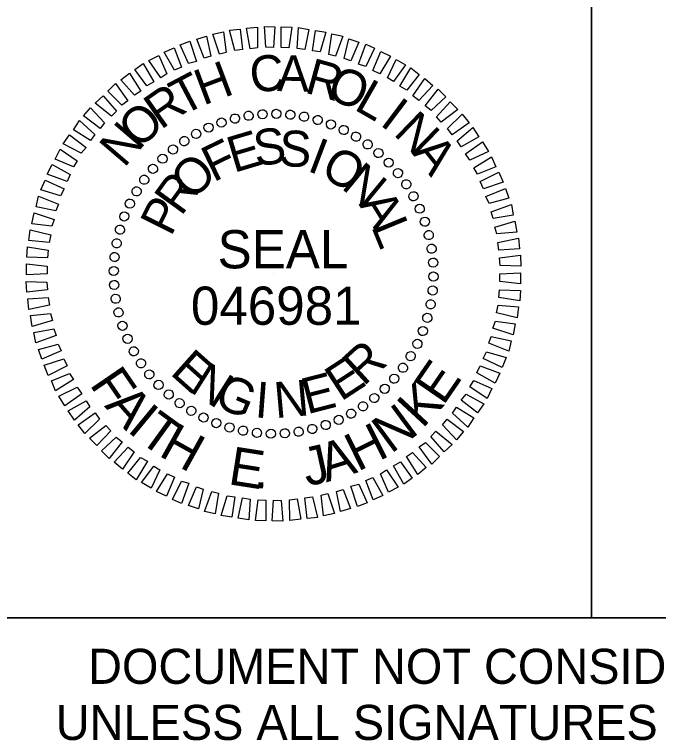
# Model space of a CAD drawing. Extents: x 1629787 to 1631995, y 1166253 to 1167353.
# Drawn here: x 1631263.8 to 1631364.8, y 1167171.6 to 1167285.5 of the extents above; entities that cross this region are included whole.
import ezdxf

# ---------------------------------------------------------------- set-up
doc = ezdxf.new("R2010")
doc.units = 0
for name, color, linetype in [('Sheet PE Seal Cell', 7, 'Continuous'), ('Sheet Profile CELL', 7, 'Continuous'), ('Sheet Sticker Exception Certification CELL', 7, 'Continuous')]:
    doc.layers.add(name, color=color, linetype=linetype)

msp = doc.modelspace()

# ---------------------------------------------------------------- linework, layer by layer
at = {"layer": 'Sheet PE Seal Cell'}
for p, q in [((1631300.53, 1167269.56), (1631300.53, 1167269.56)), ((1631302.68, 1167269.86), (1631302.68, 1167269.86)), ((1631304.88, 1167269.91), (1631304.88, 1167269.91)), ((1631307.08, 1167269.76), (1631307.08, 1167269.76)), ((1631309.23, 1167269.41), (1631309.23, 1167269.41)), ((1631296.23, 1167268.56), (1631296.23, 1167268.56)), ((1631298.33, 1167269.16), (1631298.33, 1167269.16)), ((1631311.33, 1167268.96), (1631311.33, 1167268.96)), ((1631313.43, 1167268.26), (1631313.43, 1167268.26)), ((1631294.23, 1167267.76), (1631294.23, 1167267.76)), ((1631315.43, 1167267.36), (1631315.43, 1167267.36)), ((1631292.28, 1167266.76), (1631292.28, 1167266.76)), ((1631317.38, 1167266.36), (1631317.38, 1167266.36)), ((1631290.38, 1167265.61), (1631290.38, 1167265.61)), ((1631319.18, 1167265.11), (1631319.18, 1167265.11)), ((1631288.63, 1167264.36), (1631288.63, 1167264.36)), ((1631320.93, 1167263.76), (1631320.93, 1167263.76)), ((1631286.98, 1167262.86), (1631286.98, 1167262.86)), ((1631285.48, 1167261.31), (1631285.48, 1167261.31)), ((1631322.48, 1167262.26), (1631322.48, 1167262.26)), ((1631323.98, 1167260.61), (1631323.98, 1167260.61)), ((1631284.13, 1167259.56), (1631284.13, 1167259.56)), ((1631325.23, 1167258.86), (1631325.23, 1167258.86)), ((1631282.88, 1167257.76), (1631282.88, 1167257.76)), ((1631326.38, 1167256.96), (1631326.38, 1167256.96)), ((1631281.88, 1167255.81), (1631281.88, 1167255.81)), ((1631327.38, 1167255.01), (1631327.38, 1167255.01)), ((1631280.98, 1167253.81), (1631280.98, 1167253.81)), ((1631328.18, 1167253.01), (1631328.18, 1167253.01)), ((1631280.28, 1167251.71), (1631280.28, 1167251.71)), ((1631328.78, 1167250.91), (1631328.78, 1167250.91)), ((1631279.83, 1167249.61), (1631279.83, 1167249.61)), ((1631329.18, 1167248.71), (1631329.18, 1167248.71)), ((1631279.48, 1167247.46), (1631279.48, 1167247.46)), ((1631329.48, 1167246.56), (1631329.48, 1167246.56)), ((1631279.33, 1167245.26), (1631279.33, 1167245.26)), ((1631304.43, 1167244.81), (1631304.43, 1167244.81)), ((1631329.53, 1167244.36), (1631329.53, 1167244.36)), ((1631279.38, 1167243.06), (1631279.38, 1167243.06)), ((1631329.38, 1167242.16), (1631329.38, 1167242.16)), ((1631279.68, 1167240.91), (1631279.68, 1167240.91)), ((1631329.03, 1167240.01), (1631329.03, 1167240.01)), ((1631280.08, 1167238.71), (1631280.08, 1167238.71)), ((1631328.58, 1167237.91), (1631328.58, 1167237.91)), ((1631280.68, 1167236.61), (1631280.68, 1167236.61)), ((1631327.88, 1167235.81), (1631327.88, 1167235.81)), ((1631281.48, 1167234.61), (1631281.48, 1167234.61)), ((1631326.98, 1167233.81), (1631326.98, 1167233.81)), ((1631282.48, 1167232.66), (1631282.48, 1167232.66)), ((1631325.98, 1167231.86), (1631325.98, 1167231.86)), ((1631283.63, 1167230.76), (1631283.63, 1167230.76)), ((1631324.73, 1167230.06), (1631324.73, 1167230.06)), ((1631284.88, 1167229.01), (1631284.88, 1167229.01)), ((1631323.38, 1167228.31), (1631323.38, 1167228.31)), ((1631286.38, 1167227.36), (1631286.38, 1167227.36)), ((1631321.88, 1167226.76), (1631321.88, 1167226.76)), ((1631287.93, 1167225.86), (1631287.93, 1167225.86)), ((1631320.23, 1167225.26), (1631320.23, 1167225.26)), ((1631289.68, 1167224.51), (1631289.68, 1167224.51)), ((1631318.48, 1167224.01), (1631318.48, 1167224.01)), ((1631291.48, 1167223.26), (1631291.48, 1167223.26)), ((1631316.58, 1167222.86), (1631316.58, 1167222.86)), ((1631293.43, 1167222.26), (1631293.43, 1167222.26)), ((1631314.63, 1167221.86), (1631314.63, 1167221.86)), ((1631295.43, 1167221.36), (1631295.43, 1167221.36)), ((1631297.53, 1167220.66), (1631297.53, 1167220.66)), ((1631310.53, 1167220.46), (1631310.53, 1167220.46)), ((1631312.63, 1167221.06), (1631312.63, 1167221.06)), ((1631299.63, 1167220.21), (1631299.63, 1167220.21)), ((1631301.78, 1167219.86), (1631301.78, 1167219.86)), ((1631303.98, 1167219.71), (1631303.98, 1167219.71)), ((1631306.18, 1167219.76), (1631306.18, 1167219.76)), ((1631308.33, 1167220.06), (1631308.33, 1167220.06))]:
    msp.add_line(p, q, dxfattribs=at)
for points in [[(1631298.33, 1167279.81), (1631297.53, 1167283.01), (1631299.18, 1167283.16), (1631299.53, 1167279.96)], [(1631300.73, 1167280.11), (1631300.18, 1167283.31), (1631301.88, 1167283.51), (1631301.93, 1167280.26)], [(1631303.23, 1167280.36), (1631302.98, 1167283.61), (1631304.63, 1167283.56), (1631304.43, 1167280.31)], [(1631305.63, 1167280.31), (1631305.63, 1167283.56), (1631307.28, 1167283.51), (1631306.83, 1167280.26)], [(1631308.13, 1167280.16), (1631308.33, 1167283.41), (1631309.98, 1167283.11), (1631309.33, 1167279.96)], [(1631310.53, 1167279.76), (1631310.98, 1167282.96), (1631312.63, 1167282.71), (1631311.73, 1167279.61)], [(1631293.53, 1167278.61), (1631292.38, 1167281.61), (1631293.93, 1167282.06), (1631294.58, 1167278.96)], [(1631295.93, 1167279.26), (1631294.88, 1167282.41), (1631296.58, 1167282.76), (1631296.98, 1167279.51)], [(1631313.08, 1167279.21), (1631313.58, 1167282.46), (1631315.28, 1167282.06), (1631314.13, 1167278.96)], [(1631291.08, 1167277.81), (1631289.78, 1167280.71), (1631291.28, 1167281.31), (1631292.33, 1167278.11)], [(1631315.48, 1167278.56), (1631316.23, 1167281.66), (1631317.78, 1167281.16), (1631316.53, 1167278.21)], [(1631317.73, 1167277.66), (1631318.88, 1167280.81), (1631320.28, 1167280.21), (1631318.88, 1167277.31)], [(1631288.88, 1167276.76), (1631287.28, 1167279.56), (1631288.83, 1167280.26), (1631289.98, 1167277.21)], [(1631319.98, 1167276.71), (1631321.23, 1167279.66), (1631322.78, 1167278.96), (1631321.08, 1167276.16)], [(1631286.73, 1167275.56), (1631284.88, 1167278.26), (1631286.43, 1167279.06), (1631287.68, 1167276.16)], [(1631322.28, 1167275.56), (1631323.63, 1167278.41), (1631325.13, 1167277.56), (1631323.23, 1167274.96)], [(1631284.53, 1167274.31), (1631282.68, 1167276.86), (1631283.98, 1167277.81), (1631285.63, 1167274.91)], [(1631282.63, 1167272.81), (1631280.48, 1167275.21), (1631281.83, 1167276.26), (1631283.58, 1167273.46)], [(1631324.23, 1167274.21), (1631325.98, 1167277.11), (1631327.28, 1167276.06), (1631325.33, 1167273.61)], [(1631326.28, 1167272.71), (1631328.13, 1167275.46), (1631329.43, 1167274.36), (1631327.23, 1167272.01)], [(1631280.63, 1167271.26), (1631278.43, 1167273.46), (1631279.63, 1167274.66), (1631281.58, 1167271.96)], [(1631328.18, 1167271.16), (1631330.23, 1167273.76), (1631331.43, 1167272.56), (1631329.13, 1167270.41)], [(1631278.98, 1167269.51), (1631276.43, 1167271.56), (1631277.68, 1167272.71), (1631279.78, 1167270.31)], [(1631329.98, 1167269.41), (1631332.13, 1167271.76), (1631333.33, 1167270.56), (1631330.73, 1167268.61)], [(1631277.23, 1167267.61), (1631274.63, 1167269.56), (1631275.73, 1167270.86), (1631277.93, 1167268.51)], [(1631331.73, 1167267.61), (1631334.03, 1167269.86), (1631335.08, 1167268.51), (1631332.43, 1167266.61)], [(1631275.73, 1167265.71), (1631273.03, 1167267.41), (1631273.98, 1167268.86), (1631276.38, 1167266.66)], [(1631333.23, 1167265.66), (1631335.68, 1167267.76), (1631336.63, 1167266.31), (1631333.83, 1167264.71)], [(1631274.23, 1167263.71), (1631271.43, 1167265.21), (1631272.43, 1167266.61), (1631275.03, 1167264.61)], [(1631334.53, 1167263.61), (1631337.18, 1167265.51), (1631338.13, 1167264.01), (1631335.23, 1167262.61)], [(1631273.03, 1167261.56), (1631270.18, 1167262.81), (1631270.93, 1167264.36), (1631273.63, 1167262.51)], [(1631335.83, 1167261.41), (1631338.63, 1167263.16), (1631339.28, 1167261.61), (1631336.43, 1167260.46)], [(1631272.03, 1167259.26), (1631268.93, 1167260.41), (1631269.68, 1167261.96), (1631272.53, 1167260.36)], [(1631336.83, 1167259.26), (1631339.78, 1167260.76), (1631340.43, 1167259.16), (1631337.33, 1167258.16)], [(1631271.03, 1167257.06), (1631267.93, 1167257.96), (1631268.58, 1167259.51), (1631271.58, 1167258.11)], [(1631337.73, 1167256.91), (1631340.78, 1167258.21), (1631341.33, 1167256.66), (1631338.23, 1167255.86)], [(1631270.28, 1167254.66), (1631267.18, 1167255.31), (1631267.53, 1167256.96), (1631270.68, 1167255.71)], [(1631338.53, 1167254.51), (1631341.73, 1167255.66), (1631342.03, 1167254.01), (1631338.88, 1167253.46)], [(1631269.63, 1167252.26), (1631266.53, 1167252.66), (1631266.88, 1167254.36), (1631270.03, 1167253.31)], [(1631339.13, 1167252.11), (1631342.28, 1167253.06), (1631342.58, 1167251.36), (1631339.43, 1167251.06)], [(1631269.23, 1167249.71), (1631266.03, 1167250.01), (1631266.23, 1167251.71), (1631269.48, 1167250.91)], [(1631339.58, 1167249.71), (1631342.83, 1167250.41), (1631342.98, 1167248.71), (1631339.78, 1167248.51)], [(1631268.98, 1167247.31), (1631265.73, 1167247.41), (1631265.83, 1167249.06), (1631269.08, 1167248.51)], [(1631339.88, 1167247.31), (1631343.13, 1167247.71), (1631343.23, 1167246.01), (1631339.98, 1167246.11)], [(1631268.93, 1167244.81), (1631265.68, 1167244.66), (1631265.68, 1167246.36), (1631268.93, 1167246.01)], [(1631339.93, 1167244.81), (1631343.18, 1167244.96), (1631343.18, 1167243.26), (1631339.93, 1167243.61)], [(1631268.98, 1167242.31), (1631265.73, 1167241.91), (1631265.63, 1167243.61), (1631268.88, 1167243.51)], [(1631339.88, 1167242.31), (1631343.13, 1167242.21), (1631343.03, 1167240.56), (1631339.78, 1167241.11)], [(1631269.28, 1167239.91), (1631266.03, 1167239.21), (1631265.88, 1167240.91), (1631269.08, 1167241.11)], [(1631339.63, 1167239.91), (1631342.83, 1167239.61), (1631342.63, 1167237.91), (1631339.38, 1167238.71)], [(1631269.73, 1167237.51), (1631266.58, 1167236.56), (1631266.28, 1167238.26), (1631269.43, 1167238.56)], [(1631339.23, 1167237.36), (1631342.33, 1167236.96), (1631341.98, 1167235.26), (1631338.83, 1167236.31)], [(1631270.33, 1167235.11), (1631267.13, 1167233.96), (1631266.83, 1167235.61), (1631269.98, 1167236.16)], [(1631338.58, 1167234.96), (1631341.68, 1167234.31), (1631341.33, 1167232.66), (1631338.18, 1167233.91)], [(1631271.13, 1167232.71), (1631268.08, 1167231.41), (1631267.53, 1167232.96), (1631270.63, 1167233.76)], [(1631337.83, 1167232.56), (1631340.93, 1167231.66), (1631340.28, 1167230.11), (1631337.28, 1167231.51)], [(1631272.03, 1167230.36), (1631269.08, 1167228.86), (1631268.43, 1167230.46), (1631271.53, 1167231.46)], [(1631336.83, 1167230.36), (1631339.93, 1167229.21), (1631339.18, 1167227.66), (1631336.33, 1167229.26)], [(1631273.03, 1167228.21), (1631270.23, 1167226.46), (1631269.58, 1167228.01), (1631272.43, 1167229.16)], [(1631335.83, 1167228.06), (1631338.68, 1167226.81), (1631337.93, 1167225.26), (1631335.23, 1167227.11)], [(1631274.33, 1167226.01), (1631271.68, 1167224.11), (1631270.73, 1167225.61), (1631273.63, 1167227.01)], [(1631275.63, 1167223.96), (1631273.18, 1167221.86), (1631272.23, 1167223.31), (1631275.03, 1167224.91)], [(1631334.63, 1167225.91), (1631337.43, 1167224.41), (1631336.43, 1167223.01), (1631333.83, 1167225.01)], [(1631333.13, 1167223.91), (1631335.83, 1167222.21), (1631334.88, 1167220.76), (1631332.48, 1167222.96)], [(1631277.13, 1167222.01), (1631274.83, 1167219.76), (1631273.78, 1167221.11), (1631276.43, 1167223.01)], [(1631331.63, 1167222.01), (1631334.23, 1167220.06), (1631333.13, 1167218.76), (1631330.93, 1167221.11)], [(1631278.88, 1167220.21), (1631276.73, 1167217.86), (1631275.53, 1167219.06), (1631278.13, 1167221.01)], [(1631280.68, 1167218.46), (1631278.63, 1167215.86), (1631277.43, 1167217.06), (1631279.73, 1167219.21)], [(1631329.88, 1167220.11), (1631332.43, 1167218.06), (1631331.18, 1167216.91), (1631329.08, 1167219.31)], [(1631328.23, 1167218.36), (1631330.43, 1167216.16), (1631329.23, 1167214.96), (1631327.28, 1167217.66)], [(1631282.58, 1167216.91), (1631280.73, 1167214.16), (1631279.43, 1167215.26), (1631281.63, 1167217.61)], [(1631284.63, 1167215.41), (1631282.88, 1167212.51), (1631281.58, 1167213.56), (1631283.53, 1167216.01)], [(1631326.23, 1167216.81), (1631328.38, 1167214.41), (1631327.03, 1167213.36), (1631325.28, 1167216.16)], [(1631286.58, 1167214.06), (1631285.23, 1167211.21), (1631283.73, 1167212.06), (1631285.63, 1167214.66)], [(1631324.33, 1167215.31), (1631326.18, 1167212.76), (1631324.88, 1167211.81), (1631323.23, 1167214.71)], [(1631288.88, 1167212.91), (1631287.63, 1167209.96), (1631286.08, 1167210.66), (1631287.78, 1167213.46)], [(1631322.13, 1167214.06), (1631323.98, 1167211.36), (1631322.43, 1167210.56), (1631321.18, 1167213.46)], [(1631291.13, 1167211.96), (1631289.98, 1167208.81), (1631288.58, 1167209.41), (1631289.98, 1167212.31)], [(1631319.98, 1167212.86), (1631321.58, 1167210.06), (1631320.03, 1167209.36), (1631318.88, 1167212.41)], [(1631293.38, 1167211.06), (1631292.63, 1167207.96), (1631291.08, 1167208.46), (1631292.33, 1167211.41)], [(1631317.78, 1167211.81), (1631319.08, 1167208.91), (1631317.58, 1167208.31), (1631316.53, 1167211.51)], [(1631295.78, 1167210.41), (1631295.28, 1167207.16), (1631293.58, 1167207.56), (1631294.73, 1167210.66)], [(1631298.33, 1167209.86), (1631297.88, 1167206.66), (1631296.23, 1167206.91), (1631297.13, 1167210.01)], [(1631312.93, 1167210.36), (1631313.98, 1167207.21), (1631312.28, 1167206.86), (1631311.88, 1167210.11)], [(1631315.33, 1167211.01), (1631316.48, 1167208.01), (1631314.93, 1167207.56), (1631314.28, 1167210.66)], [(1631300.73, 1167209.46), (1631300.53, 1167206.21), (1631298.88, 1167206.51), (1631299.53, 1167209.66)], [(1631303.23, 1167209.31), (1631303.23, 1167206.06), (1631301.58, 1167206.11), (1631302.03, 1167209.36)], [(1631305.63, 1167209.26), (1631305.88, 1167206.01), (1631304.23, 1167206.06), (1631304.43, 1167209.31)], [(1631308.13, 1167209.51), (1631308.68, 1167206.31), (1631306.98, 1167206.11), (1631306.93, 1167209.36)], [(1631310.53, 1167209.81), (1631311.33, 1167206.61), (1631309.68, 1167206.46), (1631309.33, 1167209.66)]]:
    msp.add_lwpolyline(points, close=True, dxfattribs=at)
for centre, major_axis in [((1631300.51, 1167269.59), (-0.113, 0.711)), ((1631302.68, 1167269.83), (-0.05, 0.718)), ((1631304.87, 1167269.89), (0.013, 0.72)), ((1631307.06, 1167269.76), (0.075, 0.716)), ((1631296.27, 1167268.53), (-0.234, 0.681)), ((1631298.37, 1167269.15), (-0.174, 0.699)), ((1631309.22, 1167269.43), (0.137, 0.707)), ((1631311.35, 1167268.92), (0.198, 0.692)), ((1631294.23, 1167267.73), (-0.293, 0.658)), ((1631313.42, 1167268.23), (0.258, 0.672)), ((1631315.43, 1167267.36), (0.316, 0.647)), ((1631292.28, 1167266.75), (-0.349, 0.63)), ((1631317.35, 1167266.31), (0.371, 0.617)), ((1631290.41, 1167265.61), (-0.403, 0.597)), ((1631319.18, 1167265.1), (0.423, 0.582)), ((1631288.65, 1167264.31), (-0.453, 0.56)), ((1631287.01, 1167262.86), (-0.5, 0.518)), ((1631320.89, 1167263.74), (0.472, 0.543)), ((1631322.48, 1167262.24), (0.518, 0.5)), ((1631285.51, 1167261.27), (-0.543, 0.472)), ((1631323.93, 1167260.6), (0.56, 0.453)), ((1631284.14, 1167259.56), (-0.582, 0.423)), ((1631325.23, 1167258.84), (0.597, 0.403)), ((1631282.94, 1167257.73), (-0.617, 0.371)), ((1631326.37, 1167256.97), (0.63, 0.349)), ((1631281.89, 1167255.81), (-0.647, 0.316)), ((1631327.35, 1167255.02), (0.658, 0.293)), ((1631281.02, 1167253.8), (-0.672, 0.258)), ((1631328.15, 1167252.98), (0.681, 0.234)), ((1631280.33, 1167251.73), (-0.692, 0.198)), ((1631328.77, 1167250.88), (0.699, 0.174)), ((1631279.82, 1167249.6), (-0.707, 0.137)), ((1631329.21, 1167248.74), (0.711, 0.113)), ((1631279.49, 1167247.44), (-0.716, 0.075)), ((1631329.45, 1167246.56), (0.718, 0.05)), ((1631279.36, 1167245.25), (-0.72, 0.013)), ((1631329.51, 1167244.38), (0.72, -0.013)), ((1631279.42, 1167243.06), (-0.718, -0.05)), ((1631329.38, 1167242.19), (0.716, -0.075)), ((1631279.66, 1167240.89), (-0.711, -0.113)), ((1631329.05, 1167240.03), (0.707, -0.137)), ((1631280.1, 1167238.75), (-0.699, -0.174)), ((1631328.54, 1167237.9), (0.692, -0.198)), ((1631280.72, 1167236.65), (-0.681, -0.234)), ((1631327.85, 1167235.83), (0.672, -0.258)), ((1631281.52, 1167234.61), (-0.658, -0.293)), ((1631326.98, 1167233.82), (0.647, -0.316)), ((1631282.5, 1167232.66), (-0.63, -0.349)), ((1631325.93, 1167231.9), (0.617, -0.371)), ((1631283.64, 1167230.79), (-0.597, -0.403)), ((1631324.72, 1167230.07), (0.582, -0.423)), ((1631284.94, 1167229.03), (-0.56, -0.453)), ((1631323.36, 1167228.36), (0.543, -0.472)), ((1631286.39, 1167227.39), (-0.518, -0.5)), ((1631321.86, 1167226.77), (0.5, -0.518)), ((1631287.98, 1167225.89), (-0.472, -0.543)), ((1631320.22, 1167225.32), (0.453, -0.56)), ((1631289.69, 1167224.52), (-0.423, -0.582)), ((1631318.46, 1167224.02), (0.403, -0.597)), ((1631291.52, 1167223.32), (-0.371, -0.617)), ((1631316.59, 1167222.88), (0.349, -0.63)), ((1631293.44, 1167222.27), (-0.316, -0.647)), ((1631314.64, 1167221.9), (0.293, -0.658)), ((1631295.45, 1167221.4), (-0.258, -0.672)), ((1631297.52, 1167220.71), (-0.198, -0.692)), ((1631312.6, 1167221.1), (0.234, -0.681)), ((1631299.65, 1167220.2), (-0.137, -0.707)), ((1631301.81, 1167219.87), (-0.075, -0.716)), ((1631304, 1167219.74), (-0.013, -0.72)), ((1631306.18, 1167219.8), (0.05, -0.718)), ((1631308.36, 1167220.04), (0.113, -0.711)), ((1631310.5, 1167220.48), (0.174, -0.699))]:
    msp.add_ellipse(centre, major_axis=major_axis, ratio=0.999708, dxfattribs=at)
at = {"layer": 'Sheet Profile CELL'}
msp.add_line((1631354.31, 1167303.35), (1631354.31, 1167190.9), dxfattribs=at)
for points in [[(1631254.26, 1167303.35), (1631354.31, 1167303.35), (1631354.31, 1167190.85), (1631254.26, 1167190.85)], [(1631354.31, 1167303.35), (1631454.31, 1167303.35), (1631454.31, 1167190.85), (1631354.31, 1167190.85)]]:
    msp.add_lwpolyline(points, close=True, dxfattribs=at)
at = {"layer": 'Sheet Sticker Exception Certification CELL'}
msp.add_line((1631254.26, 1167190.85), (1631454.3, 1167190.85), dxfattribs=at)

# ---------------------------------------------------------------- texts
at = {"layer": 'Sheet PE Seal Cell'}
for s, height, rotation, p in [('C', 5.64, 6.2199, (1631300.98, 1167273.16)), ('A', 5.64, 359.0203, (1631304.93, 1167273.46)), ('R', 5.64, 344.6211, (1631309.13, 1167273.26)), ('H', 5.64, 20.6195, (1631293.38, 1167271.16)), ('T', 5.64, 27.8198, (1631290.13, 1167269.51)), ('O', 5.64, 337.4212, (1631312.48, 1167272.51)), ('L', 5.64, 330.2209, (1631316.88, 1167270.66)), ('R', 5.64, 35.0205, (1631286.73, 1167267.31)), ('I', 5.64, 323.0201, (1631320.93, 1167268.26)), ('O', 5.64, 42.2217, (1631283.28, 1167264.21)), ('N', 5.64, 315.8189, (1631323.08, 1167266.71)), ('N', 5.64, 49.4235, (1631280.98, 1167261.31)), ('E', 5.64, 16.6111, (1631298.18, 1167260.61)), ('S', 5.64, 7.2556, (1631301.63, 1167261.66)), ('S', 5.64, 357.9004, (1631305.23, 1167261.71)), ('F', 5.64, 25.967, (1631294.98, 1167259.11)), ('I', 5.64, 339.1896, (1631309.53, 1167261.01)), ('A', 5.64, 308.6172, (1631326.03, 1167263.76)), ('O', 5.64, 329.8335, (1631311.53, 1167260.31)), ('O', 5.64, 44.6812, (1631291.68, 1167256.16)), ('N', 5.64, 320.4766, (1631314.88, 1167258.31)), ('R', 5.64, 54.0397, (1631289.93, 1167253.71)), ('P', 5.64, 63.3989, (1631288.33, 1167250.51)), ('A', 5.64, 301.7603, (1631317.73, 1167255.71)), ('L', 5.64, 292.4009, (1631319.68, 1167252.26)), ('SEAL', 5.998, 360, (1631295.64, 1167245.66)), ('E', 5.64, 318.2769, (1631288.03, 1167229.16)), ('R', 5.64, 42.4814, (1631318.53, 1167227.06)), ('E', 5.64, 33.1241, (1631314.98, 1167224.71)), ('N', 5.64, 327.634, (1631291.03, 1167226.46)), ('E', 6, 55.493, (1631331.04, 1167224.02)), ('F', 6, 304.4142, (1631275.47, 1167227.47)), ('E', 5.64, 14.4118, (1631309.68, 1167222.76)), ('G', 5.64, 336.9902, (1631294.83, 1167224.21)), ('I', 5.64, 355.7012, (1631301.38, 1167222.31)), ('N', 5.64, 5.0564, (1631304.73, 1167222.16)), ('K', 6, 47.2091, (1631327.76, 1167220.41)), ('A', 6, 311.4309, (1631277.8, 1167224.06)), ('I', 6, 320.2712, (1631281.31, 1167220.21)), ('N', 6, 36.4833, (1631322.81, 1167216.49)), ('T', 6, 324.0731, (1631282.99, 1167218.74)), ('H', 6, 26.4993, (1631317.62, 1167213.73)), ('H', 6, 330.8733, (1631286.23, 1167216.38)), ('J', 6, 12.4012, (1631309.66, 1167211.46)), ('A', 6, 17.659, (1631312.69, 1167212.08)), ('E', 6, 351.0577, (1631297.16, 1167211.84)), ('.', 6, 358.167, (1631301.29, 1167211.2))]:
    msp.add_text(s, height=height, rotation=rotation, dxfattribs=at).set_placement(p)
msp.add_text('046981', height=5.998, dxfattribs=at).set_placement((1631291.46, 1167236.81))
at = {"layer": 'Sheet Sticker Exception Certification CELL'}
for s, p in [('DOCUMENT NOT CONSIDERED FINAL', (1631275.33, 1167180.51)), ('UNLESS ALL SIGNATURES COMPLETED', (1631270.26, 1167171.71))]:
    msp.add_text(s, height=5.5, rotation=360, dxfattribs=at).set_placement(p)

doc.saveas('drawing.dxf')
